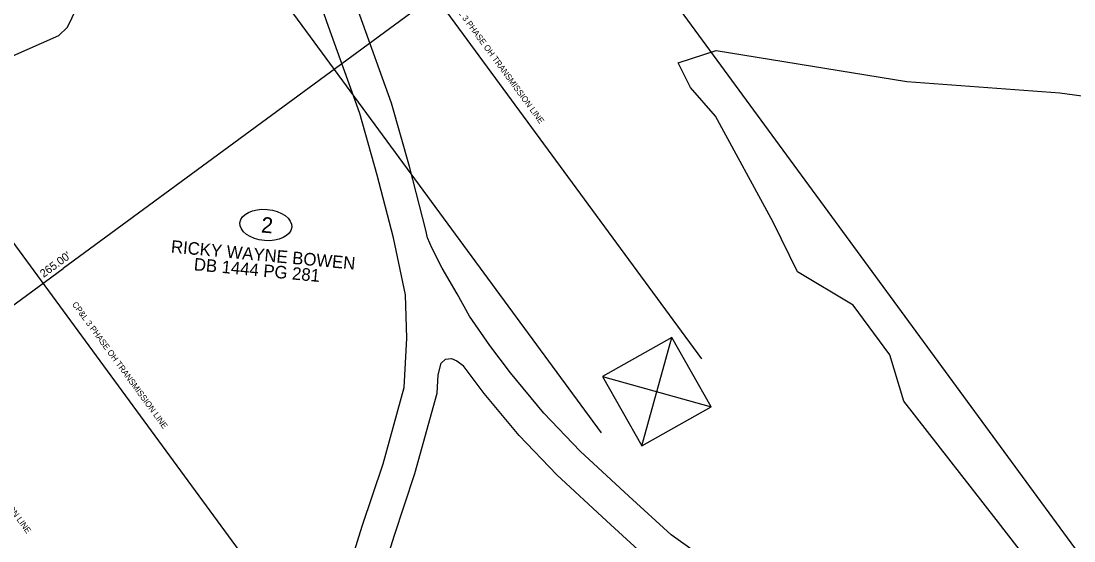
# Model space of a CAD drawing. Extents: x 2060057 to 2062431, y 911685 to 913703.
# Drawn here: x 2060964.3 to 2061216.8, y 912533.1 to 912657.7 of the extents above; entities that cross this region are included whole.
import ezdxf

# ---------------------------------------------------------------- set-up
doc = ezdxf.new("R2010")
doc.units = 0
for name, color, linetype in [('Exist Hydro Stream or Body of Water', 7, 'Continuous'), ('Exist Property Owner Number Topo CELL', 7, 'Continuous'), ('Exist Property Owner Text', 7, 'Continuous'), ('Exist Right of Way Line', 7, 'Continuous'), ('Exist Right of Way Width CELL', 7, 'Continuous'), ('Exist Roads Soil', 7, 'Continuous'), ('Exist Utilities Power Tower CELL', 7, 'Continuous'), ('Exist Utilities Power UG Cable', 7, 'Continuous'), ('Exist Utilities Power UG Cable Text', 7, 'Continuous'), ('Exist Vegetation Woods Line', 7, 'Continuous')]:
    doc.layers.add(name, color=color, linetype=linetype)

msp = doc.modelspace()

# ---------------------------------------------------------------- linework, layer by layer
at = {"layer": 'Exist Hydro Stream or Body of Water'}
for points in [[(2060973.25, 912654.18), (2060975.4, 912656.3), (2060978.82, 912663.48), (2060982.77, 912671.49), (2060984.48, 912680.26), (2060985.77, 912688.73), (2060987.17, 912702.89)], [(2060973.25, 912654.18), (2060961.52, 912649), (2060946.34, 912644.77), (2060940.96, 912643.7), (2060931.5, 912643.28), (2060925.67, 912642.01), (2060922.27, 912639.32), (2060916.97, 912634.43), (2060911.4, 912630.07), (2060904.68, 912625.12), (2060900.78, 912624.42), (2060892.16, 912622.37), (2060888.71, 912620.12), (2060882.89, 912616.64), (2060877.51, 912611.95), (2060869.79, 912606.07), (2060864.04, 912600.9), (2060856.53, 912596.9), (2060848.02, 912593.44), (2060841.95, 912591.92), (2060836.52, 912587.91)]]:
    msp.add_lwpolyline(points, dxfattribs=at)
at = {"layer": 'Exist Property Owner Number Topo CELL'}
msp.add_ellipse((2061022.99, 912608.84), major_axis=(6.2, -0.55), ratio=0.60241, dxfattribs=at)
at = {"layer": 'Exist Right of Way Line'}
msp.add_lwpolyline([(2060856.35, 913022.77), (2061454.48, 912207.78)], dxfattribs=at)
at = {"layer": 'Exist Right of Way Width CELL'}
for p in [(2061100.07, 912690.69), (2060886.43, 912533.9)]:
    msp.add_line(p, (2060974.36, 912598.44), dxfattribs=at)
at = {"layer": 'Exist Roads Soil'}
for points in [[(2061061.77, 912605.8), (2061061.4, 912607.61), (2061057.44, 912622.9), (2061053.14, 912638.05), (2061045.52, 912659.13), (2061038.34, 912679.8)], [(2060999.14, 912422.48), (2061019.51, 912465.68), (2061029.38, 912489.7), (2061038.68, 912512.75), (2061046.11, 912536.69), (2061051.09, 912551.62), (2061056.14, 912569.88), (2061056.84, 912581.68), (2061056.45, 912592.08), (2061053.6, 912605.8), (2061049.71, 912620.8), (2061045.52, 912635.6), (2061037.98, 912656.46), (2061030.78, 912677.17)], [(2061076.73, 912579.99), (2061071.86, 912586.96), (2061068.88, 912592.37), (2061065.25, 912598.46), (2061062.85, 912603.23), (2061061.77, 912605.8)], [(2061246.77, 912376.37), (2061224.59, 912414.45), (2061198.42, 912453.9), (2061180.76, 912479.26), (2061163.28, 912499.92), (2061154.62, 912507.77), (2061135.56, 912523.62), (2061120.23, 912534.58), (2061110.08, 912543.81), (2061098.41, 912554.63), (2061089.68, 912563.73), (2061081.64, 912573.41), (2061076.73, 912579.99)], [(2061064.33, 912572.94), (2061065.08, 912575.72), (2061066.06, 912576.67), (2061067.55, 912576.87), (2061068.79, 912576.26), (2061070.32, 912575.2)], [(2061239.85, 912372.34), (2061217.8, 912410.23), (2061191.8, 912449.4), (2061174.41, 912474.38), (2061157.52, 912494.35), (2061149.37, 912501.73), (2061130.67, 912517.28), (2061115.19, 912528.34), (2061104.67, 912537.91), (2061092.8, 912548.92), (2061083.71, 912558.39), (2061075.35, 912568.46), (2061070.32, 912575.2)], [(2061001.87, 912409.47), (2061026.84, 912462.47), (2061036.79, 912486.69), (2061046.22, 912510.06), (2061053.73, 912534.24), (2061058.74, 912549.29), (2061064.07, 912568.56), (2061064.33, 912572.94)]]:
    msp.add_lwpolyline(points, dxfattribs=at)
at = {"layer": 'Exist Utilities Power Tower CELL'}
msp.add_lwpolyline([(2061113.15, 912555.88), (2061129.78, 912565.26), (2061120.4, 912581.9), (2061103.77, 912572.52), (2061113.15, 912555.88), (2061120.4, 912581.9), (2061103.77, 912572.52), (2061129.78, 912565.26)], dxfattribs=at)
at = {"layer": 'Exist Utilities Power UG Cable'}
for points in [[(2060304.19, 913696.4), (2061127.5, 912576.77)], [(2060280.08, 913678.67), (2061103.4, 912559.04)], [(2060725.83, 912927), (2061324.02, 912111.8)]]:
    msp.add_lwpolyline(points, dxfattribs=at)
at = {"layer": 'Exist Vegetation Woods Line'}
msp.add_lwpolyline([(2061229.59, 912497.71), (2061198.16, 912538.24), (2061176, 912566.62), (2061172.63, 912577.76), (2061163.86, 912589.65), (2061150.49, 912597.6), (2061144.65, 912609.5), (2061130.82, 912634.94), (2061124.88, 912641.79), (2061121.91, 912647.73), (2061131.02, 912650.65), (2061176.71, 912643.27), (2061213.45, 912640.49), (2061249.85, 912635.54), (2061276.08, 912635.46), (2061285.85, 912632.29), (2061291.56, 912626.1), (2061296.4, 912615.32), (2061300.04, 912603.98), (2061306, 912575.14), (2061310.7, 912553.21), (2061306.48, 912535.66), (2061302.91, 912522.66)], dxfattribs=at)

# ---------------------------------------------------------------- texts
at = {"layer": 'Exist Property Owner Number Topo CELL'}
msp.add_text('2', height=3.75, rotation=354.9115, dxfattribs=at).set_placement((2061021.76, 912607.07))
at = {"layer": 'Exist Property Owner Text'}
for s, p in [('RICKY WAYNE BOWEN', (2061000.14, 912602.24)), ('DB 1444 PG 281', (2061005.63, 912597.99))]:
    msp.add_text(s, height=3, rotation=354.6833, dxfattribs=at).set_placement(p)
at = {"layer": 'Exist Right of Way Width CELL'}
msp.add_text("265.00'", height=1.92, rotation=36.275, dxfattribs=at).set_placement((2060969.69, 912596.15))
at = {"layer": 'Exist Utilities Power UG Cable Text'}
for rotation, p in [(306.3285, (2061066.71, 912662.89)), (306.2709, (2060976.44, 912589.79)), (306.2709, (2060943.69, 912564.7))]:
    msp.add_text('CP&L 3 PHASE OH TRANSMISSION LINE', height=1.44, rotation=rotation, dxfattribs=at).set_placement(p)

doc.saveas('drawing.dxf')
